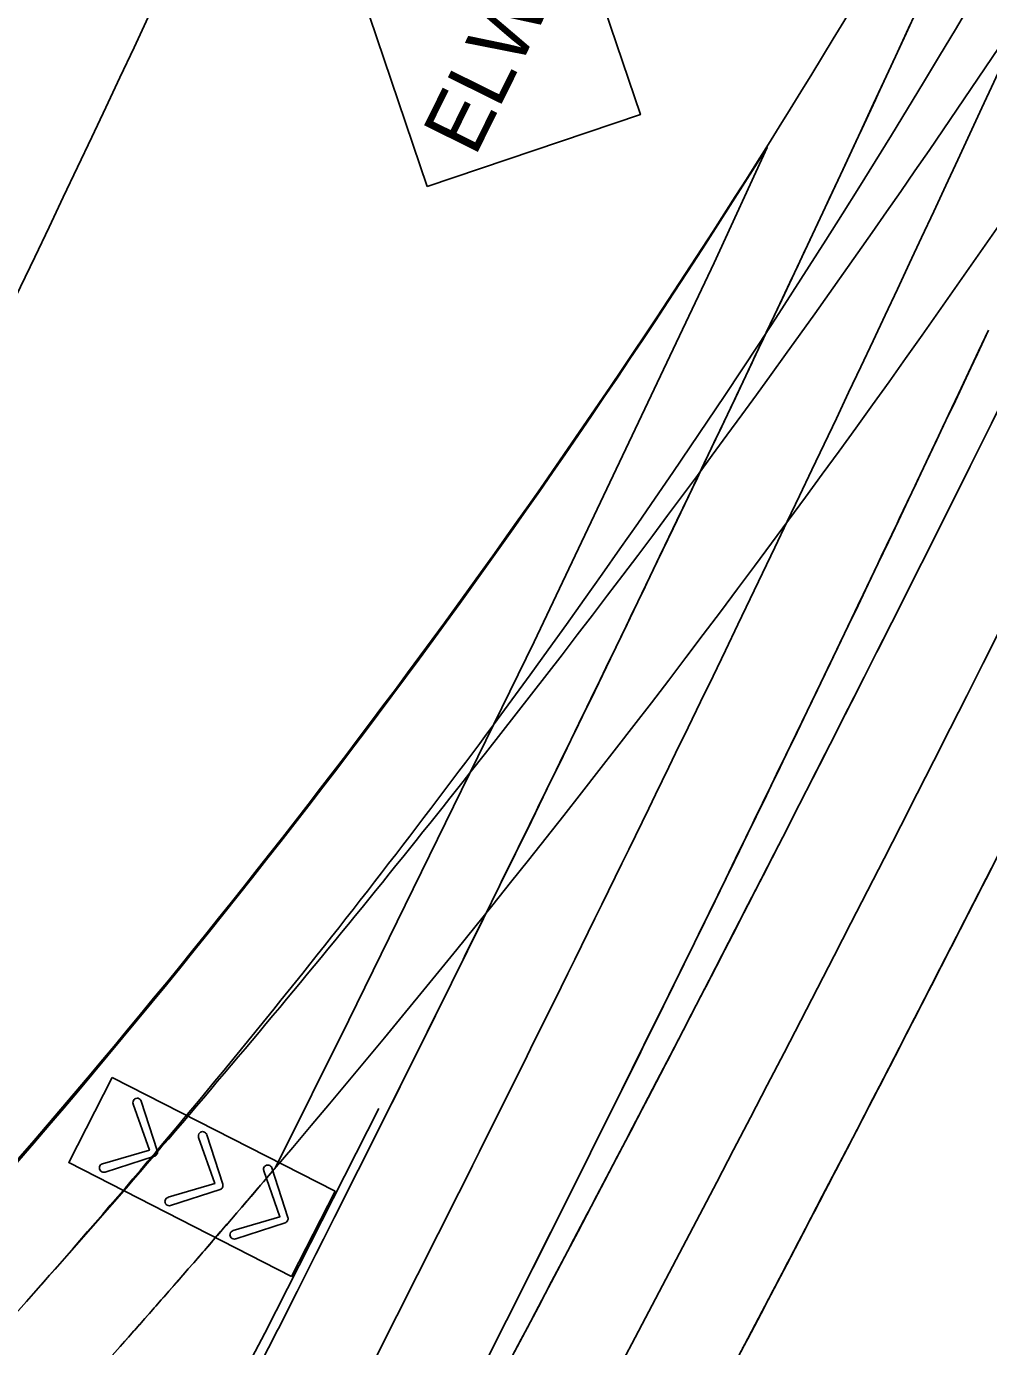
# Model space of a CAD drawing. Extents: x 14097936 to 14128734, y 8632000 to 8683104.
# Drawn here: x 14119604.7 to 14119720.1, y 8669688.3 to 8669846.7 of the extents above; entities that cross this region are included whole.
import ezdxf

# ---------------------------------------------------------------- set-up
doc = ezdxf.new("R2010")
doc.units = 0
for name, color, linetype in [('dsnPaintExistingBrokenLaneLineWhite', 7, 'Continuous'), ('dsnPaintExistingChannelizingLaneWhite', 7, 'Continuous'), ('dsnPaintExistingChannelizingLaneYellow', 7, 'Continuous'), ('dsnPaintExistingDoubleCenterYellow', 7, 'Continuous'), ('dsnPaintExistingEdgeLineRightWhite', 7, 'Continuous'), ('dsnPaintExistingNoPassingYellow', 7, 'Continuous'), ('dsnPaintPlaceBrokenLaneWhite', 7, 'Continuous'), ('dsnPaintPlaceEdgeLineRightWhite', 7, 'Continuous'), ('dsnPavementRmvl', 7, 'Continuous'), ('dsnShadingPaved', 7, 'Continuous'), ('dsnStdLabel', 7, 'Continuous'), ('dsnStdLineWork', 7, 'Continuous'), ('dsnStgShadingPropPav', 7, 'Continuous'), ('dsnTapeRemoveChannelizingLaneWhite', 7, 'Continuous'), ('dsnTapeRemoveChannelizingLaneYellow', 7, 'Continuous')]:
    doc.layers.add(name, color=color, linetype=linetype)

msp = doc.modelspace()

# ---------------------------------------------------------------- linework, layer by layer
at = {"layer": 'dsnPaintExistingBrokenLaneLineWhite'}
for centre, radius, start, end in [((14115457.93, 8671918.7), 4772.49, 331.51238, 334.87343), ((14115415.47, 8671832.28), 4743.93, 332.6713, 334.0913)]:
    msp.add_arc(centre, radius, start, end, dxfattribs=at)
at = {"layer": 'dsnPaintExistingChannelizingLaneWhite'}
for centre, radius, start, end in [((14118856.61, 8670357.32), 988, 318.43496, 327.62991), ((14118559.34, 8670625.19), 1412.15, 318.29842, 319.58068)]:
    msp.add_arc(centre, radius, start, end, dxfattribs=at)
at = {"layer": 'dsnPaintExistingChannelizingLaneYellow'}
for centre, radius, start, end in [((14118856.5, 8670357.19), 1000, 318.43496, 323.53736), ((14118559.34, 8670625.19), 1400.15, 318.29726, 321.68516)]:
    msp.add_arc(centre, radius, start, end, dxfattribs=at)
at = {"layer": 'dsnPaintExistingDoubleCenterYellow'}
msp.add_line((14119583.96, 8669670.32), (14119604.7, 8669693.72), dxfattribs=at)
at = {"layer": 'dsnPaintExistingEdgeLineRightWhite'}
msp.add_lwpolyline([(14119647, 8669716.86), (14119633.3, 8669689.93), (14119607.29, 8669640.58), (14119581.23, 8669591.8), (14119571.48, 8669571.41)], dxfattribs=at)
msp.add_arc((14115457.93, 8671918.7), 4784.49, 331.51238, 334.87343, dxfattribs=at)
msp.add_open_spline([(14119690.33, 8669687.52), (14119690.42, 8669687.68), (14119690.54, 8669687.92), (14119690.69, 8669688.2), (14119690.75, 8669688.32), (14119690.8, 8669688.4), (14119690.82, 8669688.44), (14119690.92, 8669688.64), (14119691.01, 8669688.8), (14119691.11, 8669689), (14119691.13, 8669689.04), (14119691.17, 8669689.1), (14119691.18, 8669689.12), (14119691.19, 8669689.15), (14119691.2, 8669689.17), (14119691.21, 8669689.18), (14119691.21, 8669689.19), (14119691.22, 8669689.2), (14119691.26, 8669689.29), (14119691.3, 8669689.37), (14119691.68, 8669690.09), (14119692.02, 8669690.73), (14119693.03, 8669692.65), (14119693.71, 8669693.93), (14119695.73, 8669697.78), (14119699.76, 8669705.49), (14119706.45, 8669718.35), (14119713.09, 8669731.23), (14119717.06, 8669738.97), (14119719.03, 8669742.84), (14119719.69, 8669744.13), (14119720.68, 8669746.07), (14119721.01, 8669746.71), (14119721.67, 8669748), (14119721.99, 8669748.65), (14119722.32, 8669749.29)], degree=3, dxfattribs=at)
msp.add_open_spline([(14119690.33, 8669687.52), (14119690.42, 8669687.68), (14119690.54, 8669687.92), (14119690.69, 8669688.2), (14119690.75, 8669688.32), (14119690.8, 8669688.4), (14119690.82, 8669688.44), (14119690.92, 8669688.64), (14119691.01, 8669688.8), (14119691.11, 8669689), (14119691.13, 8669689.04), (14119691.17, 8669689.1), (14119691.18, 8669689.12), (14119691.19, 8669689.15), (14119691.2, 8669689.17), (14119691.21, 8669689.18), (14119691.21, 8669689.19), (14119691.22, 8669689.2), (14119691.26, 8669689.29), (14119691.3, 8669689.37), (14119691.68, 8669690.09), (14119692.02, 8669690.73), (14119693.03, 8669692.65), (14119693.71, 8669693.93), (14119695.73, 8669697.78), (14119699.76, 8669705.49), (14119706.45, 8669718.35), (14119713.09, 8669731.23), (14119717.06, 8669738.97), (14119719.03, 8669742.84), (14119719.69, 8669744.13), (14119720.68, 8669746.07), (14119721.01, 8669746.71), (14119721.67, 8669748), (14119721.99, 8669748.65), (14119722.32, 8669749.29)], degree=3, dxfattribs=at)
at = {"layer": 'dsnPaintExistingNoPassingYellow'}
for centre, radius, start, end in [((14115457.93, 8671918.7), 4760.49, 331.51238, 334.1332), ((14115415.47, 8671832.28), 4755.93, 332.6713, 334.83903)]:
    msp.add_arc(centre, radius, start, end, dxfattribs=at)
at = {"layer": 'dsnPaintPlaceBrokenLaneWhite'}
msp.add_arc((14115416.69, 8671831.7), 4742.58, 334.09122, 339.391, dxfattribs=at)
at = {"layer": 'dsnPaintPlaceEdgeLineRightWhite'}
msp.add_arc((14115464.82, 8671807.98), 4676.93, 333.43454, 336.83378, dxfattribs=at)
at = {"layer": 'dsnPavementRmvl'}
for p, q in [((14119687.21, 8669818.32), (14119693.57, 8669832.16)), ((14119665.62, 8669772.85), (14119687.21, 8669818.32)), ((14119643.4, 8669727.45), (14119665.62, 8669772.85)), ((14119634.53, 8669709.69), (14119643.4, 8669727.45))]:
    msp.add_line(p, q, dxfattribs=at)
for centre, radius, start, end in [((14118856.27, 8670356.65), 988, 317.73115, 327.93685), ((14118559.48, 8670625.12), 1412, 318.43496, 319.58497)]:
    msp.add_arc(centre, radius, start, end, dxfattribs=at)
at = {"layer": 'dsnShadingPaved'}
for points in [[(14119710.74, 8669846.89), (14119708.96, 8669843.04), (14119708.65, 8669842.38), (14119706.86, 8669838.51), (14119706.56, 8669837.87), (14119704.93, 8669834.36), (14119704.76, 8669833.99), (14119704.46, 8669833.36), (14119702.65, 8669829.47), (14119702.36, 8669828.85), (14119701.01, 8669825.98), (14119700.54, 8669824.95), (14119700.25, 8669824.35), (14119698.42, 8669820.44), (14119698.14, 8669819.85), (14119697.08, 8669817.6), (14119696.67, 8669816.71), (14119696.29, 8669815.93), (14119696.02, 8669815.35), (14119694.17, 8669811.41), (14119693.9, 8669810.85), (14119693.14, 8669809.24), (14119692.03, 8669806.91), (14119691.77, 8669806.36), (14119689.9, 8669802.4), (14119689.64, 8669801.86), (14119689.18, 8669800.88), (14119687.76, 8669797.9), (14119687.51, 8669797.38), (14119685.61, 8669793.39), (14119685.37, 8669792.89), (14119685.2, 8669792.53), (14119683.46, 8669788.89), (14119683.22, 8669788.4), (14119681.3, 8669784.4), (14119681.07, 8669783.92), (14119679.14, 8669779.9), (14119678.92, 8669779.44), (14119677.19, 8669775.85), (14119676.98, 8669775.41), (14119676.76, 8669774.96), (14119674.8, 8669770.92), (14119674.59, 8669770.48), (14119673.16, 8669767.53), (14119672.63, 8669766.43), (14119672.42, 8669766.01), (14119670.45, 8669761.94), (14119670.25, 8669761.53), (14119669.12, 8669759.21), (14119668.27, 8669757.46), (14119668.07, 8669757.06), (14119666.08, 8669752.98), (14119665.89, 8669752.59), (14119665.06, 8669750.9), (14119663.88, 8669748.5), (14119663.7, 8669748.13), (14119661.68, 8669744.02), (14119661.51, 8669743.66), (14119660.98, 8669742.59), (14119659.48, 8669739.55), (14119659.31, 8669739.2), (14119657.27, 8669735.08), (14119657.11, 8669734.74), (14119656.89, 8669734.3), (14119655.06, 8669730.61), (14119654.9, 8669730.29), (14119652.84, 8669726.14), (14119652.69, 8669725.83), (14119650.62, 8669721.68), (14119650.47, 8669721.38), (14119648.65, 8669717.72), (14119648.39, 8669717.22), (14119648.25, 8669716.93), (14119646.16, 8669712.75), (14119646.02, 8669712.48), (14119644.5, 8669709.45), (14119643.92, 8669708.3), (14119643.79, 8669708.04), (14119641.68, 8669703.84), (14119641.56, 8669703.59), (14119640.35, 8669701.19), (14119639.44, 8669699.39), (14119639.32, 8669699.15), (14119637.19, 8669694.93), (14119637.08, 8669694.71), (14119636.17, 8669692.93), (14119634.94, 8669690.49), (14119634.83, 8669690.28), (14119632.67, 8669686.04)], [(14119658.6, 8669684.1), (14119660.74, 8669688.33), (14119660.87, 8669688.57), (14119661.78, 8669690.38), (14119662.99, 8669692.8), (14119663.12, 8669693.05), (14119665.24, 8669697.26), (14119665.37, 8669697.53), (14119665.96, 8669698.69), (14119667.48, 8669701.73), (14119667.62, 8669702.01), (14119669.72, 8669706.2), (14119669.86, 8669706.49), (14119670.12, 8669707), (14119671.95, 8669710.67), (14119672.1, 8669710.98), (14119674.18, 8669715.14), (14119674.33, 8669715.46), (14119676.4, 8669719.62), (14119676.56, 8669719.95), (14119678.4, 8669723.65), (14119678.62, 8669724.1), (14119678.79, 8669724.45), (14119680.83, 8669728.58), (14119681.01, 8669728.94), (14119682.51, 8669731.99), (14119683.04, 8669733.07), (14119683.22, 8669733.44), (14119685.24, 8669737.55), (14119685.43, 8669737.94), (14119686.61, 8669740.34), (14119687.44, 8669742.04), (14119687.64, 8669742.44), (14119689.64, 8669746.53), (14119689.84, 8669746.94), (14119690.69, 8669748.69), (14119691.83, 8669751.03), (14119692.03, 8669751.45), (14119694.01, 8669755.52), (14119694.22, 8669755.95), (14119694.76, 8669757.06), (14119696.19, 8669760.02), (14119696.41, 8669760.47), (14119698.37, 8669764.52), (14119698.59, 8669764.98), (14119698.81, 8669765.43), (14119700.54, 8669769.02), (14119700.77, 8669769.5), (14119702.7, 8669773.52), (14119702.94, 8669774.01), (14119704.87, 8669778.03), (14119705.11, 8669778.53), (14119706.85, 8669782.18), (14119707.02, 8669782.54), (14119707.27, 8669783.06), (14119709.17, 8669787.05), (14119709.43, 8669787.58), (14119710.85, 8669790.58), (14119711.32, 8669791.57), (14119711.58, 8669792.11), (14119713.46, 8669796.08), (14119713.73, 8669796.64), (14119714.83, 8669798.98), (14119715.6, 8669800.6), (14119715.87, 8669801.17), (14119717.73, 8669805.12), (14119718.01, 8669805.7), (14119718.38, 8669806.49), (14119718.8, 8669807.39), (14119719.86, 8669809.64), (14119720.14, 8669810.24)], [(14119658.6, 8669684.1), (14119660.74, 8669688.33), (14119660.87, 8669688.57), (14119661.78, 8669690.38), (14119662.99, 8669692.8), (14119663.12, 8669693.05), (14119665.24, 8669697.26), (14119665.37, 8669697.53), (14119665.96, 8669698.69), (14119667.48, 8669701.73), (14119667.62, 8669702.01), (14119669.72, 8669706.2), (14119669.86, 8669706.49), (14119670.12, 8669707), (14119671.95, 8669710.67), (14119672.1, 8669710.98), (14119674.18, 8669715.14), (14119674.33, 8669715.46), (14119676.4, 8669719.62), (14119676.56, 8669719.95), (14119678.4, 8669723.65), (14119678.62, 8669724.1), (14119678.79, 8669724.45), (14119680.83, 8669728.58), (14119681.01, 8669728.94), (14119682.51, 8669731.99), (14119683.04, 8669733.07), (14119683.22, 8669733.44), (14119685.24, 8669737.55), (14119685.43, 8669737.94), (14119686.61, 8669740.34), (14119687.44, 8669742.04), (14119687.64, 8669742.44), (14119689.64, 8669746.53), (14119689.84, 8669746.94), (14119690.69, 8669748.69), (14119691.83, 8669751.03), (14119692.03, 8669751.45), (14119694.01, 8669755.52), (14119694.22, 8669755.95), (14119694.76, 8669757.06), (14119696.19, 8669760.02), (14119696.41, 8669760.47), (14119698.37, 8669764.52), (14119698.59, 8669764.98), (14119698.81, 8669765.43), (14119700.54, 8669769.02), (14119700.77, 8669769.5), (14119702.7, 8669773.52), (14119702.94, 8669774.01), (14119704.87, 8669778.03), (14119705.11, 8669778.53), (14119706.85, 8669782.18), (14119707.02, 8669782.54), (14119707.27, 8669783.06), (14119709.17, 8669787.05), (14119709.43, 8669787.58), (14119710.85, 8669790.58), (14119711.32, 8669791.57), (14119711.58, 8669792.11), (14119713.46, 8669796.08), (14119713.73, 8669796.64), (14119714.83, 8669798.98), (14119715.6, 8669800.6), (14119715.87, 8669801.17), (14119717.73, 8669805.12), (14119718.01, 8669805.7), (14119718.38, 8669806.49), (14119718.8, 8669807.39), (14119719.86, 8669809.64), (14119720.14, 8669810.24)], [(14119662.99, 8669687.16), (14119664.07, 8669689.19), (14119665.01, 8669690.97), (14119665.33, 8669691.58), (14119667.34, 8669695.38), (14119667.67, 8669696), (14119668.42, 8669697.42), (14119669.67, 8669699.79), (14119670, 8669700.43), (14119671.99, 8669704.21), (14119672.33, 8669704.86), (14119672.75, 8669705.65), (14119674.31, 8669708.63), (14119674.66, 8669709.29), (14119676.62, 8669713.04), (14119676.98, 8669713.72), (14119677.07, 8669713.89), (14119678.93, 8669717.47), (14119679.29, 8669718.15), (14119681.24, 8669721.89), (14119681.37, 8669722.15), (14119681.6, 8669722.59), (14119683.54, 8669726.31), (14119683.91, 8669727.03), (14119685.66, 8669730.41), (14119685.83, 8669730.74), (14119686.21, 8669731.47), (14119688.12, 8669735.17), (14119688.5, 8669735.91), (14119689.92, 8669738.67), (14119690.4, 8669739.6), (14119690.79, 8669740.36), (14119692.69, 8669744.04), (14119693.08, 8669744.81), (14119694.18, 8669746.95), (14119694.96, 8669748.48), (14119695.36, 8669749.26), (14119697.23, 8669752.92), (14119697.64, 8669753.72), (14119698.41, 8669755.23), (14119699.5, 8669757.36), (14119699.91, 8669758.17), (14119701.76, 8669761.81), (14119702.18, 8669762.63), (14119702.63, 8669763.53), (14119704.02, 8669766.25), (14119704.44, 8669767.09), (14119706.27, 8669770.7), (14119706.7, 8669771.56), (14119706.84, 8669771.83), (14119708.52, 8669775.16), (14119708.96, 8669776.02), (14119710.76, 8669779.61), (14119711.03, 8669780.14), (14119711.2, 8669780.49), (14119713, 8669784.07), (14119713.45, 8669784.96), (14119715.2, 8669788.46), (14119715.69, 8669789.43), (14119717.47, 8669792.99), (14119717.93, 8669793.91), (14119719.36, 8669796.78), (14119719.69, 8669797.45), (14119720.16, 8669798.39)], [(14119720.16, 8669798.39), (14119719.69, 8669797.45), (14119719.36, 8669796.78), (14119717.93, 8669793.91), (14119717.47, 8669792.99), (14119715.69, 8669789.43), (14119715.2, 8669788.46), (14119713.45, 8669784.96), (14119713, 8669784.07), (14119711.2, 8669780.49), (14119711.03, 8669780.14), (14119710.76, 8669779.61), (14119708.96, 8669776.02), (14119708.52, 8669775.16), (14119706.84, 8669771.83), (14119706.7, 8669771.56), (14119706.27, 8669770.7), (14119704.44, 8669767.09), (14119704.02, 8669766.25), (14119702.63, 8669763.53), (14119702.18, 8669762.63), (14119701.76, 8669761.81), (14119699.91, 8669758.17), (14119699.5, 8669757.36), (14119698.41, 8669755.23), (14119697.64, 8669753.72), (14119697.23, 8669752.92), (14119695.36, 8669749.26), (14119694.96, 8669748.48), (14119694.18, 8669746.95), (14119693.08, 8669744.81), (14119692.69, 8669744.04), (14119690.79, 8669740.36), (14119690.4, 8669739.6), (14119689.92, 8669738.67), (14119688.5, 8669735.91), (14119688.12, 8669735.17), (14119686.21, 8669731.47), (14119685.83, 8669730.74), (14119685.66, 8669730.41), (14119683.91, 8669727.03), (14119683.54, 8669726.31), (14119681.6, 8669722.59), (14119681.37, 8669722.15), (14119681.24, 8669721.89), (14119679.29, 8669718.15), (14119678.93, 8669717.47), (14119677.07, 8669713.89), (14119676.98, 8669713.72), (14119676.62, 8669713.04), (14119674.66, 8669709.29), (14119674.31, 8669708.63), (14119672.75, 8669705.65), (14119672.33, 8669704.86), (14119671.99, 8669704.21), (14119670, 8669700.43), (14119669.67, 8669699.79), (14119668.42, 8669697.42), (14119667.67, 8669696), (14119667.34, 8669695.38), (14119665.33, 8669691.58), (14119665.01, 8669690.97), (14119664.07, 8669689.19), (14119662.99, 8669687.16)], [(14119720.88, 8669746.46), (14119719.79, 8669744.33), (14119719.01, 8669742.8), (14119718.6, 8669742), (14119716.73, 8669738.33), (14119716.32, 8669737.54), (14119715.53, 8669736), (14119714.43, 8669733.85), (14119714.03, 8669733.07), (14119712.13, 8669729.38), (14119711.74, 8669728.62), (14119711.26, 8669727.68), (14119709.83, 8669724.91), (14119709.44, 8669724.16), (14119707.52, 8669720.45), (14119707.14, 8669719.71), (14119706.97, 8669719.37), (14119705.21, 8669715.98), (14119704.84, 8669715.26), (14119702.9, 8669711.52), (14119702.66, 8669711.07), (14119702.53, 8669710.81), (14119700.57, 8669707.06), (14119700.21, 8669706.36), (14119698.34, 8669702.78), (14119698.25, 8669702.6), (14119697.89, 8669701.92), (14119695.92, 8669698.15), (14119695.57, 8669697.48), (14119694, 8669694.5), (14119693.58, 8669693.7), (14119693.24, 8669693.04), (14119691.24, 8669689.25), (14119690.9, 8669688.61), (14119689.65, 8669686.22)]]:
    msp.add_lwpolyline(points, dxfattribs=at)
at = {"layer": 'dsnStdLabel'}
for points in [[(14119652.79, 8669827.45), (14119678.36, 8669836.1), (14119669.71, 8669861.68), (14119644.14, 8669853.03)], [(14119615.01, 8669720.59), (14119641.73, 8669706.94), (14119636.5, 8669696.72), (14119609.79, 8669710.38)]]:
    msp.add_lwpolyline(points, close=True, dxfattribs=at)
msp.add_arc((14116987.75, 8671075.02), 2903.66, 332.64356, 337.66488, dxfattribs=at)
at = {"layer": 'dsnStdLineWork'}
for p, q in [((14119620.4, 8669711.81), (14119618.49, 8669717.74)), ((14119628.26, 8669707.8), (14119626.34, 8669713.72)), ((14119636.07, 8669703.8), (14119634.15, 8669709.73))]:
    msp.add_line(p, q, dxfattribs=at)
for points in [[(14119617.51, 8669717.43), (14119617.52, 8669717.4), (14119619.46, 8669711.88), (14119613.84, 8669710.22)], [(14119625.36, 8669713.41), (14119625.37, 8669713.38), (14119627.31, 8669707.86), (14119621.7, 8669706.21)], [(14119614.13, 8669709.23), (14119614.15, 8669709.24), (14119620.07, 8669711.16), (14119620.08, 8669711.16)], [(14119633.17, 8669709.42), (14119633.18, 8669709.39), (14119635.12, 8669703.87), (14119629.51, 8669702.21)], [(14119621.98, 8669705.22), (14119622, 8669705.22), (14119627.93, 8669707.14), (14119627.93, 8669707.14)], [(14119629.79, 8669701.23), (14119629.81, 8669701.23), (14119635.74, 8669703.15), (14119635.74, 8669703.15)]]:
    msp.add_lwpolyline(points, dxfattribs=at)
for centre, start, end in [((14119618, 8669717.58), 17.6389, 197.8225), ((14119625.85, 8669713.57), 17.6389, 197.8225), ((14119619.92, 8669711.65), 288.3101, 18.7584), ((14119613.98, 8669709.73), 105.5597, 286.7189), ((14119633.66, 8669709.57), 17.6389, 197.8225), ((14119627.77, 8669707.63), 288.3101, 18.7584), ((14119621.84, 8669705.71), 105.5597, 286.7189), ((14119635.58, 8669703.64), 288.3101, 18.7584), ((14119629.64, 8669701.72), 105.5597, 286.7189)]:
    msp.add_arc(centre, 0.515, start, end, dxfattribs=at)
at = {"layer": 'dsnStgShadingPropPav'}
for p, q in [((14119687.21, 8669818.32), (14119693.57, 8669832.16)), ((14119665.62, 8669772.85), (14119687.21, 8669818.32)), ((14119643.4, 8669727.45), (14119665.62, 8669772.85)), ((14119634.53, 8669709.69), (14119643.4, 8669727.45))]:
    msp.add_line(p, q, dxfattribs=at)
for centre, radius, start, end in [((14118856.27, 8670356.65), 988, 317.73115, 327.93685), ((14118559.48, 8670625.12), 1412, 318.43496, 319.58497)]:
    msp.add_arc(centre, radius, start, end, dxfattribs=at)
at = {"layer": 'dsnTapeRemoveChannelizingLaneWhite'}
for centre, radius, start, end in [((14118559.34, 8670625.19), 1412.15, 319.58068, 337.35767), ((14118856.61, 8670357.32), 988, 327.62991, 336.79664)]:
    msp.add_arc(centre, radius, start, end, dxfattribs=at)
at = {"layer": 'dsnTapeRemoveChannelizingLaneYellow'}
for centre, radius, start, end in [((14118559.34, 8670625.19), 1400.15, 321.68516, 337.35766), ((14118856.5, 8670357.19), 1000, 323.53736, 337.142)]:
    msp.add_arc(centre, radius, start, end, dxfattribs=at)

# ---------------------------------------------------------------- texts
at = {"layer": 'dsnStdLabel'}
msp.add_text('ELW4', height=7.2, rotation=63.6912, dxfattribs=at).set_placement((14119658.52, 8669830.91))

doc.saveas('drawing.dxf')
